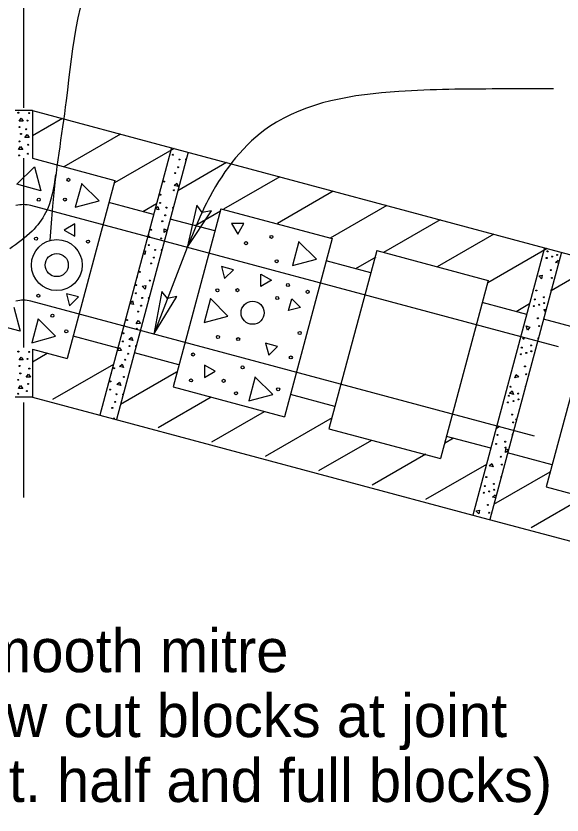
# Model space of a CAD drawing. Extents: x 0 to 2.83, y -0.03 to 1.83.
# Drawn here: x 0.4777 to 0.6421, y 0.6876 to 0.928 of the extents above; entities that cross this region are included whole.
import ezdxf

# ---------------------------------------------------------------- set-up
doc = ezdxf.new("R2010")
doc.units = 0
for name, color, linetype in [('50', 7, 'Continuous'), ('51', 7, 'Continuous'), ('52', 7, 'Continuous'), ('54', 7, 'Continuous'), ('55', 7, 'Continuous'), ('57', 7, 'Continuous'), ('58', 7, 'Continuous')]:
    doc.layers.add(name, color=color, linetype=linetype)

msp = doc.modelspace()

# ---------------------------------------------------------------- linework, layer by layer
at = {"layer": '50'}
for p, q in [((0.4774566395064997, 0.899610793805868), (0.4826566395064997, 0.899610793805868)), ((0.4826566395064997, 0.8995654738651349), (0.524515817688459, 0.8883493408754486)), ((0.4826566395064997, 0.8995654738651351), (0.4826566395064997, 0.8851923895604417)), ((0.524515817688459, 0.8883493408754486), (0.5029561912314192, 0.8078877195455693)), ((0.524515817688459, 0.8883493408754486), (0.6368207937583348, 0.8582573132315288)), ((0.4826566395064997, 0.8851923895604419), (0.5075122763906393, 0.8785323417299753)), ((0.529538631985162, 0.8870034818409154), (0.5079790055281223, 0.8065418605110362)), ((0.5075122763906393, 0.8785323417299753), (0.49313919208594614, 0.8248912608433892)), ((0.5191171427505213, 0.8682334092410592), (0.505706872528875, 0.8718266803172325)), ((0.5393556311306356, 0.8699999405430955), (0.5249825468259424, 0.8163588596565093)), ((0.5393556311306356, 0.8699999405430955), (0.5728893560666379, 0.8610146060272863)), ((0.5375502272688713, 0.8632942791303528), (0.5241399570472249, 0.8668875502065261)), ((0.5728893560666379, 0.8610146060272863), (0.5585162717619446, 0.8073735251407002)), ((0.5862996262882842, 0.857421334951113), (0.571926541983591, 0.8037802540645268)), ((0.5862996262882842, 0.857421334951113), (0.6198172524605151, 0.8484403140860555)), ((0.6368207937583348, 0.8582573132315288), (0.615261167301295, 0.7777956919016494)), ((0.6418597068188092, 0.8569071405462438), (0.6203000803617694, 0.7764455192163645)), ((0.6368207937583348, 0.8582573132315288), (0.7491418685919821, 0.8281609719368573)), ((0.5844942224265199, 0.8507156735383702), (0.5710839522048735, 0.8543089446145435)), ((0.6198172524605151, 0.8484403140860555), (0.6054441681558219, 0.7947992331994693)), ((0.6314382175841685, 0.8381370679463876), (0.6180279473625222, 0.8417303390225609)), ((0.6516767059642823, 0.839903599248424), (0.6373036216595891, 0.7862625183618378)), ((0.649871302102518, 0.8331979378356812), (0.6364610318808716, 0.8367912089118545)), ((0.5083387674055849, 0.82800796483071), (0.4949284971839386, 0.8316012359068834)), ((0.4826566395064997, 0.8277000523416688), (0.49313919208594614, 0.8248912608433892)), ((0.4826566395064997, 0.8277000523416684), (0.4826566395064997, 0.8133269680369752)), ((0.5267718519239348, 0.8230688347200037), (0.5133615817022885, 0.8266621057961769)), ((0.5249825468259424, 0.8163588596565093), (0.5585162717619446, 0.8073735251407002)), ((0.4774566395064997, 0.8133722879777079), (0.4826566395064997, 0.8133722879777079)), ((0.4826566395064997, 0.8133269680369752), (0.5029561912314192, 0.8078877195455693)), ((0.5737158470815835, 0.810490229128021), (0.5603055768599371, 0.8140835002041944)), ((0.5029561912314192, 0.8078877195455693), (0.615261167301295, 0.7777956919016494)), ((0.571926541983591, 0.8037802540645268), (0.6054441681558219, 0.7947992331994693)), ((0.6206598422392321, 0.7979116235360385), (0.6072495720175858, 0.8015048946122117)), ((0.639092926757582, 0.792972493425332), (0.6256826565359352, 0.7965657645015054)), ((0.6373036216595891, 0.7862625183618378), (0.67082124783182, 0.7772814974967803)), ((0.615261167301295, 0.7777956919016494), (0.7275822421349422, 0.7476993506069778))]:
    msp.add_line(p, q, dxfattribs=at)
for centre in [(0.493513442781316, 0.8786878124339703), (0.4845836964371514, 0.872706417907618), (0.49245140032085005, 0.8727393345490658), (0.48377012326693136, 0.8609843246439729), (0.5546186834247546, 0.8615091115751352), (0.49941355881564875, 0.8601223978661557), (0.5469472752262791, 0.8596262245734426), (0.5562011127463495, 0.8542044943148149), (0.5595652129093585, 0.8470255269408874), (0.4844703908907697, 0.8437985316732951), (0.538361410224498, 0.845452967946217), (0.5443681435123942, 0.84548092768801), (0.565494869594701, 0.8449791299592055), (0.556338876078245, 0.8431232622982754), (0.48869356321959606, 0.8378078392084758), (0.4928798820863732, 0.8330917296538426), (0.5385112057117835, 0.8314120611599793), (0.5631251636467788, 0.8326134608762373), (0.5445909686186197, 0.8307661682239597), (0.5310410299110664, 0.8261299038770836), (0.5604438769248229, 0.8252362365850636), (0.5459242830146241, 0.8222479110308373), (0.5304033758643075, 0.8183128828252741), (0.5402147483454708, 0.8182017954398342), (0.556635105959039, 0.8156581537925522), (0.5439470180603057, 0.8144768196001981)]:
    msp.add_circle(centre, 0.00045797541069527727, dxfattribs=at)
at = {"layer": '51'}
for p, q in [((0.483298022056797, 0.8825930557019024), (0.47802111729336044, 0.8773658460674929)), ((0.4832915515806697, 0.8826172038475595), (0.48521975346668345, 0.8754210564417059)), ((0.4974988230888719, 0.8776092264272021), (0.4955706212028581, 0.8704130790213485)), ((0.4974923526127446, 0.877585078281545), (0.5027692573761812, 0.8723578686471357)), ((0.48521975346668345, 0.8754210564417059), (0.47802974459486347, 0.8773336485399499)), ((0.6409597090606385, 0.8283963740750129), (0.48221876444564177, 0.8709308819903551)), ((0.4955706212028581, 0.8704130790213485), (0.5027606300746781, 0.8723256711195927)), ((0.5628759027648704, 0.8600914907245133), (0.5609477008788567, 0.8528953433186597)), ((0.5628694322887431, 0.860067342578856), (0.5681463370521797, 0.8548401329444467)), ((0.5609477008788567, 0.8528953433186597), (0.5681377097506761, 0.8548079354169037)), ((0.63377604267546, 0.801586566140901), (0.48221876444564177, 0.8421962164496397)), ((0.5362443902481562, 0.8429714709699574), (0.5343322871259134, 0.8357710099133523)), ((0.5362540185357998, 0.8429430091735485), (0.5415126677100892, 0.8377120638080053)), ((0.47704956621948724, 0.8403601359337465), (0.47896166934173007, 0.833159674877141)), ((0.4843597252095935, 0.8368804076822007), (0.4824476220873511, 0.8296799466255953)), ((0.48437151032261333, 0.8368599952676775), (0.4896301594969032, 0.831629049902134)), ((0.5343322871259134, 0.8357710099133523), (0.5415083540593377, 0.8376959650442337)), ((0.47896166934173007, 0.833159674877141), (0.47178560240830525, 0.8350846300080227)), ((0.4824476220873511, 0.8296799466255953), (0.48962368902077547, 0.8316049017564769)), ((0.549736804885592, 0.8193626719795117), (0.5478247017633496, 0.8121622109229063)), ((0.5497485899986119, 0.8193422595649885), (0.5550072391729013, 0.814111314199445)), ((0.5478247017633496, 0.8121622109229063), (0.555000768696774, 0.814087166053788))]:
    msp.add_line(p, q, dxfattribs=at)
for centre in [(0.49000834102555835, 0.8530289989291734), (0.5489396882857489, 0.838677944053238)]:
    msp.add_circle(centre, 0.0034722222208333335, dxfattribs=at)
for centre in [(0.4799720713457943, 0.8625461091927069), (0.4799720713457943, 0.8338114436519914)]:
    msp.add_arc(centre, 0.008680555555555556, 74.99999999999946, 104.99999999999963, dxfattribs=at)
at = {"layer": '52'}
for p, q in [((0.5463158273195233, 0.8655812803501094), (0.5425818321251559, 0.8655551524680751)), ((0.5425839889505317, 0.8655632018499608), (0.5444460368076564, 0.8623380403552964)), ((0.5444460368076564, 0.8623380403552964), (0.5463115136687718, 0.8655651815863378)), ((0.49540548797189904, 0.8654197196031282), (0.4921879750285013, 0.8635827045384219)), ((0.49219013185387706, 0.863574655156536), (0.4954131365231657, 0.8617206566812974)), ((0.4954131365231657, 0.8617206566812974), (0.49541942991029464, 0.8654320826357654)), ((0.539550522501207, 0.8525968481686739), (0.5405167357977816, 0.8489905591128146)), ((0.5431427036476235, 0.8516429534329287), (0.5395623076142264, 0.8525764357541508)), ((0.5405167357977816, 0.8489905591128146), (0.5431566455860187, 0.8516305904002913)), ((0.5513921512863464, 0.8466266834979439), (0.5513858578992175, 0.850338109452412)), ((0.5513997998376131, 0.8503257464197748), (0.5546173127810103, 0.8484887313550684)), ((0.554615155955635, 0.8484806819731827), (0.5513921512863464, 0.8466266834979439)), ((0.49651970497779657, 0.8434461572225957), (0.49292536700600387, 0.8443920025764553)), ((0.4929275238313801, 0.844400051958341), (0.493879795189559, 0.840806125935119)), ((0.493879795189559, 0.840806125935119), (0.49651754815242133, 0.84343810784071)), ((0.5597773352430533, 0.8393189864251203), (0.5607414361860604, 0.842917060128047)), ((0.5607392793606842, 0.8429090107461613), (0.5633696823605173, 0.8402975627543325)), ((0.563367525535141, 0.8402895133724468), (0.5597773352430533, 0.8393189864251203)), ((0.5564249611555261, 0.8285697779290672), (0.5528306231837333, 0.8295156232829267)), ((0.5528306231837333, 0.8295156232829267), (0.5537828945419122, 0.8259216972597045)), ((0.5537872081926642, 0.8259377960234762), (0.5564249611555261, 0.8285697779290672)), ((0.5344123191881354, 0.8229598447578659), (0.5344142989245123, 0.8192323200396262)), ((0.5376437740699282, 0.8211104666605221), (0.534426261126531, 0.8229474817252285)), ((0.5344142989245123, 0.8192323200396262), (0.5376416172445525, 0.8211024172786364))]:
    msp.add_line(p, q, dxfattribs=at)
at = {"layer": '54'}
for points in [[(0.529284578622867, 0.8583196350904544), (0.53656055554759, 0.8693416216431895), (0.5337844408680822, 0.8688845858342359), (0.5321086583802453, 0.8710747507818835)], [(0.5192398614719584, 0.8322764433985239), (0.5261308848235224, 0.8435431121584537), (0.5233722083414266, 0.8429904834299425), (0.5216217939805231, 0.8451214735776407)]]:
    msp.add_lwpolyline(points, close=True, dxfattribs=at)
at = {"layer": '55'}
for p, q in [((0.4799720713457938, 0.9799769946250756), (0.4799720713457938, 0.9003949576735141)), ((0.4799720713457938, 0.8852377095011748), (0.4799720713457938, 0.8282019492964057)), ((0.529284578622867, 0.8583196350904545), (0.5192398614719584, 0.8322764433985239)), ((0.4799720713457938, 0.811689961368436), (0.4799720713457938, 0.7831406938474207))]:
    msp.add_line(p, q, dxfattribs=at)
for points in [[(0.4786593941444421, 0.8963397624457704), (0.47928439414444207, 0.8972381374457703), (0.47990951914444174, 0.8963397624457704), (0.4786593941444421, 0.8963397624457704)], [(0.480439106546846, 0.8914013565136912), (0.481064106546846, 0.8922997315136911), (0.4816892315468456, 0.8914013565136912), (0.480439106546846, 0.8914013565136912)], [(0.47849809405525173, 0.8877908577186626), (0.4791230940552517, 0.8886892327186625), (0.47974821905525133, 0.8877908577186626), (0.47849809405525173, 0.8877908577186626)], [(0.5253327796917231, 0.8769874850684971), (0.5261689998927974, 0.8776934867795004), (0.5265403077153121, 0.8766639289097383), (0.5253327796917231, 0.8769874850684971)], [(0.5196089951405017, 0.8700368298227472), (0.520370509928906, 0.8706797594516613), (0.5207418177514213, 0.8696502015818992), (0.5195882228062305, 0.8699593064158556)], [(0.5223337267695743, 0.8628053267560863), (0.5223304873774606, 0.8638997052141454), (0.5232568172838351, 0.8635594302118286)], [(0.5232212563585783, 0.8634267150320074), (0.5223337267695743, 0.8628053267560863)], [(0.5161665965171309, 0.8571896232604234), (0.5166575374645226, 0.8572777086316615), (0.5164642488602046, 0.8562004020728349), (0.5160204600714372, 0.8566442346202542)], [(0.6400817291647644, 0.8538420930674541), (0.6409179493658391, 0.8545480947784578), (0.6410956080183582, 0.8540554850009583)], [(0.6409743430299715, 0.8536029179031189), (0.6400817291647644, 0.8538420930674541)], [(0.6350464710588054, 0.849756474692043), (0.6361237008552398, 0.8499497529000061), (0.6359304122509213, 0.8488724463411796), (0.6350464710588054, 0.849756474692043)], [(0.5156911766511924, 0.8466725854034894), (0.5167684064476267, 0.8468658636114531), (0.5165751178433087, 0.8457885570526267), (0.5156911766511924, 0.8466725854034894)], [(0.5119860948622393, 0.8415877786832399), (0.5127476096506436, 0.8422307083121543), (0.5131189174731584, 0.8412011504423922), (0.5119653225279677, 0.8415102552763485)], [(0.6366266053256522, 0.8396467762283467), (0.6372353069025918, 0.8396486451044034)], [(0.6370664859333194, 0.8390185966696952), (0.6366266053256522, 0.8396467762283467)], [(0.5139394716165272, 0.835384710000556), (0.5144838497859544, 0.8363340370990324), (0.5151848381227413, 0.8354935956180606), (0.5139394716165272, 0.835384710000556)], [(0.6313126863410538, 0.834708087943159), (0.6323421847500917, 0.8343368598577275), (0.6316363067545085, 0.8335005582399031), (0.6313126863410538, 0.834708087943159)], [(0.5117036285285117, 0.8306776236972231), (0.512539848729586, 0.8313836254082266), (0.5129111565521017, 0.8303540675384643), (0.5117036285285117, 0.8306776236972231)], [(0.5082741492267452, 0.8272712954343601), (0.5088184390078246, 0.8282207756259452), (0.5095195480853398, 0.8273803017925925), (0.5082741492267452, 0.8272712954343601)], [(0.4786593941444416, 0.8244743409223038), (0.47928439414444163, 0.8253727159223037), (0.47990951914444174, 0.8244743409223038), (0.4786593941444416, 0.8244743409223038)], [(0.5088360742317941, 0.8225243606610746), (0.5096722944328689, 0.8232303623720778), (0.5100436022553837, 0.8222008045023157), (0.5088360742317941, 0.8225243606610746)], [(0.4808395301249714, 0.819350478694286), (0.4814645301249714, 0.820248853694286), (0.48208965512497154, 0.819350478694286), (0.4808395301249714, 0.819350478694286)], [(0.6278833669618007, 0.8191051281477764), (0.6282544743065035, 0.820134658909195), (0.6290908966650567, 0.8194287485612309), (0.6278833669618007, 0.8191051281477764)], [(0.5080604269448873, 0.8170810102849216), (0.5088966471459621, 0.817787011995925), (0.5092679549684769, 0.8167574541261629), (0.5080604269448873, 0.8170810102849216)], [(0.47849809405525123, 0.8159254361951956), (0.4791230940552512, 0.8168238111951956), (0.47974821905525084, 0.8159254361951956), (0.47849809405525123, 0.8159254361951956)], [(0.6262363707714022, 0.8144508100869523), (0.6270725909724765, 0.8151568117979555), (0.6274438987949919, 0.8141272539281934), (0.6262363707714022, 0.8144508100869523)], [(0.5069652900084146, 0.8068134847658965), (0.5072385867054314, 0.8070442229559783), (0.5073599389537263, 0.8067077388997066)], [(0.6281080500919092, 0.8067153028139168), (0.62841109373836, 0.8067162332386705)], [(0.6283270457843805, 0.8064025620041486), (0.6281080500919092, 0.8067153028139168)], [(0.6222540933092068, 0.8037402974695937), (0.6222536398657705, 0.8038919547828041)], [(0.6224833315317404, 0.8047491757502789), (0.6232781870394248, 0.8044572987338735), (0.6222540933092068, 0.8037402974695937)], [(0.6250317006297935, 0.7966855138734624), (0.6251236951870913, 0.7977759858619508), (0.6259158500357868, 0.7974038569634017)], [(0.6258499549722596, 0.7971579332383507), (0.6250317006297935, 0.7966855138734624)], [(0.6201153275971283, 0.7926518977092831), (0.6209515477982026, 0.7933578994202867), (0.6213228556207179, 0.7923283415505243), (0.6201153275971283, 0.7926518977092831)], [(0.6211513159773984, 0.7831928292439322), (0.6219875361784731, 0.783898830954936), (0.6221651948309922, 0.7834062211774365)], [(0.6220439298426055, 0.7829536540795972), (0.6211513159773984, 0.7831928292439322)], [(0.6161160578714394, 0.7791072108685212), (0.6171932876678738, 0.7793004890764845), (0.6169999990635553, 0.7782231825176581), (0.6161160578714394, 0.7791072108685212)]]:
    msp.add_lwpolyline(points, dxfattribs=at)
for centre, radius in [((0.47843780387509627, 0.8988860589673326), 0.00015017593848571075), ((0.4817117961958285, 0.8987860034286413), 0.00015017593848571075), ((0.47880839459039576, 0.894538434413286), 0.00015017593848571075), ((0.4811621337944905, 0.8964937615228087), 0.00015017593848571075), ((0.47923930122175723, 0.8925103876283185), 0.00015017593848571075), ((0.4808136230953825, 0.8939098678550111), 0.00015017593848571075), ((0.4787494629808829, 0.8902257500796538), 0.00015017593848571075), ((0.4813941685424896, 0.8892415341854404), 0.00015017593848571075), ((0.47864891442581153, 0.8860225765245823), 0.00015017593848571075), ((0.481318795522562, 0.8865279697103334), 0.00015017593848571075), ((0.5249649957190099, 0.8862347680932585), 0.00015017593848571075), ((0.5268984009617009, 0.8848019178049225), 0.00015017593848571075), ((0.5265237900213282, 0.882493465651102), 0.00015017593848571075), ((0.5256508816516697, 0.8807150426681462), 0.00015017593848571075), ((0.5223144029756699, 0.8781633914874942), 0.00015017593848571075), ((0.5252709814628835, 0.875541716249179), 0.00015017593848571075), ((0.5212165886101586, 0.8741797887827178), 0.00015017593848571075), ((0.5210827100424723, 0.8717458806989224), 0.00015017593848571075), ((0.5230161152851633, 0.8703130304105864), 0.00015017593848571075), ((0.5226415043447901, 0.8680045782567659), 0.00015017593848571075), ((0.5217685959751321, 0.8662261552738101), 0.00015017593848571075), ((0.5184321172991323, 0.8636745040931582), 0.00015017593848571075), ((0.5178153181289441, 0.8614860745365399), 0.00015017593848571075), ((0.5213886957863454, 0.8610528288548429), 0.00015017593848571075), ((0.4900083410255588, 0.8530289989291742), 0.007657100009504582), ((0.5176814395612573, 0.8590521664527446), 0.00015017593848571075), ((0.5196148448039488, 0.8576193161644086), 0.00015017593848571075), ((0.6377260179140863, 0.8571679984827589), 0.00015017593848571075), ((0.6405883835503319, 0.8560961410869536), 0.00015017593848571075), ((0.5183673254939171, 0.8535324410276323), 0.00015017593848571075), ((0.519240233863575, 0.8553108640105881), 0.00015017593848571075), ((0.6374330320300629, 0.8551641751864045), 0.00015017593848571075), ((0.6390772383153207, 0.85557732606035), 0.00015017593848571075), ((0.5150308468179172, 0.8509807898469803), 0.00015017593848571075), ((0.6386871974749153, 0.8515044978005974), 0.00015017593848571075), ((0.6390334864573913, 0.8491553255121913), 0.00015017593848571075), ((0.5139330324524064, 0.846997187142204), 0.00015017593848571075), ((0.5179874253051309, 0.8483591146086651), 0.00015017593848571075), ((0.5137991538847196, 0.8445632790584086), 0.00015017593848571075), ((0.6343250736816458, 0.8453858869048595), 0.00015017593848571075), ((0.5157325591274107, 0.8431304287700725), 0.00015017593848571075), ((0.6338437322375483, 0.8426791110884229), 0.00015017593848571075), ((0.6366285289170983, 0.8433660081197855), 0.00015017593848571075), ((0.6367060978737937, 0.8416072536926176), 0.00015017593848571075), ((0.514485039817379, 0.8390435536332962), 0.00015017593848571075), ((0.5153579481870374, 0.840821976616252), 0.00015017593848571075), ((0.6335507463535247, 0.8406752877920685), 0.00015017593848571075), ((0.6351949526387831, 0.8410884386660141), 0.00015017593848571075), ((0.6348049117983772, 0.8370156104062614), 0.00015017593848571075), ((0.5111485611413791, 0.8364919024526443), 0.00015017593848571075), ((0.6351512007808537, 0.8346664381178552), 0.00015017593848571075), ((0.5100507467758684, 0.8325082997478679), 0.00015017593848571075), ((0.5141051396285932, 0.833870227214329), 0.00015017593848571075), ((0.509916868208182, 0.8300743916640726), 0.00015017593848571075), ((0.6304427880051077, 0.8308969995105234), 0.00015017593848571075), ((0.47843780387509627, 0.8270206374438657), 0.00015017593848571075), ((0.481711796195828, 0.8269205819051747), 0.00015017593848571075), ((0.5118502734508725, 0.8286415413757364), 0.00015017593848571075), ((0.6299614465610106, 0.8281902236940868), 0.00015017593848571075), ((0.6327462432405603, 0.8288771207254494), 0.00015017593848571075), ((0.6328238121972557, 0.8271183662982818), 0.00015017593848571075), ((0.48122375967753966, 0.8247828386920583), 0.00015017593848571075), ((0.5106027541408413, 0.8245546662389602), 0.00015017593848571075), ((0.5114756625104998, 0.8263330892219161), 0.00015017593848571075), ((0.6296684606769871, 0.8261864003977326), 0.00015017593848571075), ((0.6313126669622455, 0.8265995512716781), 0.00015017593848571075), ((0.47880839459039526, 0.8226730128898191), 0.00015017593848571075), ((0.6309226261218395, 0.8225267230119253), 0.00015017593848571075), ((0.4790306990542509, 0.8204427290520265), 0.00015017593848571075), ((0.4817417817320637, 0.8218820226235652), 0.00015017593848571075), ((0.5072662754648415, 0.8220030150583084), 0.00015017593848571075), ((0.6312689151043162, 0.8201775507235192), 0.00015017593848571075), ((0.4784080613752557, 0.8185067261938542), 0.00015017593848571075), ((0.5061684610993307, 0.8180194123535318), 0.00015017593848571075), ((0.5102228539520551, 0.819381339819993), 0.00015017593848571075), ((0.4810236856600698, 0.815116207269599), 0.00015017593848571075), ((0.4813747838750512, 0.8172757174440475), 0.00015017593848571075), ((0.5060345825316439, 0.8155855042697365), 0.00015017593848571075), ((0.6265605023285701, 0.8164081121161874), 0.00015017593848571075), ((0.4784102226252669, 0.8143116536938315), 0.00015017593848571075), ((0.5079679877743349, 0.8141526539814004), 0.00015017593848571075), ((0.626079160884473, 0.8137013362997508), 0.00015017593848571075), ((0.6288639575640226, 0.8143882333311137), 0.00015017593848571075), ((0.628941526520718, 0.8126294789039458), 0.00015017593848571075), ((0.5075933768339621, 0.81184420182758), 0.00015017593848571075), ((0.6257861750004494, 0.8116975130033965), 0.00015017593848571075), ((0.6274303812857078, 0.812110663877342), 0.00015017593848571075), ((0.5067204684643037, 0.8100657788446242), 0.00015017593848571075), ((0.6270403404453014, 0.8080378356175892), 0.00015017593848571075), ((0.627386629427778, 0.8056886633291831), 0.00015017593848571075), ((0.6226782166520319, 0.8019192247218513), 0.00015017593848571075), ((0.6221968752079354, 0.7992124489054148), 0.00015017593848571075), ((0.624981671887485, 0.7998993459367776), 0.00015017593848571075), ((0.6250592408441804, 0.7981405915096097), 0.00015017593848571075), ((0.6236390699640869, 0.7953441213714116), 0.00015017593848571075), ((0.6239853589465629, 0.7929949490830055), 0.00015017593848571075), ((0.6192769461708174, 0.7892255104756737), 0.00015017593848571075), ((0.6187956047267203, 0.7865187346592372), 0.00015017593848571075), ((0.6215804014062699, 0.7872056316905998), 0.00015017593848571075), ((0.6185026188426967, 0.784514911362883), 0.00015017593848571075), ((0.6201468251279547, 0.7849280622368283), 0.00015017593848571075), ((0.6216579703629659, 0.7854468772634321), 0.00015017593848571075), ((0.6197567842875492, 0.7808552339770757), 0.00015017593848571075), ((0.6201030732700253, 0.7785060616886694), 0.00015017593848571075)]:
    msp.add_circle(centre, radius, dxfattribs=at)
for centre, start, end in [((0.528862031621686, 0.8847332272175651), 48.94572428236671, 281.05427571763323), ((0.521401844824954, 0.8765784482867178), 240.08057103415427, 89.91942896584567), ((0.5249797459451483, 0.8702443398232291), 48.945724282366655, 281.05427571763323), ((0.5175195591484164, 0.8620895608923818), 240.08057103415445, 89.91942896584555), ((0.5215784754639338, 0.8575506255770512), 48.94572428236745, 281.05427571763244), ((0.5141182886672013, 0.8493958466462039), 240.0805710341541, 89.9194289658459), ((0.638835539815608, 0.8454579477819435), 91.29949940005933, 238.70050059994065), ((0.5176961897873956, 0.8430617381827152), 48.94572428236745, 281.05427571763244), ((0.5102360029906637, 0.8349069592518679), 240.08057103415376, 89.91942896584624), ((0.6349532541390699, 0.8309690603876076), 91.29949940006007, 238.70050059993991), ((0.5138139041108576, 0.8285728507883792), 48.94572428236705, 281.0542757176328), ((0.5063537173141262, 0.8204180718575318), 240.08057103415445, 89.91942896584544), ((0.6310709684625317, 0.8164801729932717), 91.29949940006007, 238.70050059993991), ((0.5099316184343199, 0.8140839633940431), 48.945724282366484, 281.05427571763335), ((0.6271886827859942, 0.8019912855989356), 91.29949940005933, 238.70050059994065), ((0.6237874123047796, 0.789297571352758), 91.29949940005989, 238.70050059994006)]:
    msp.add_arc(centre, 0.00015017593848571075, start, end, dxfattribs=at)
for points in [[(0.5260705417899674, 0.963329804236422), (0.5210756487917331, 0.963329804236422), (0.5056057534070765, 0.9510080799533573), (0.49282029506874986, 0.9025470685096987), (0.48869595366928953, 0.8707896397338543), (0.4879615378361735, 0.8604074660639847)], [(0.6395170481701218, 0.906018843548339), (0.6228943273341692, 0.906018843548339), (0.5929091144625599, 0.9052641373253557), (0.5540231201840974, 0.8947015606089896), (0.5360338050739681, 0.8735764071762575), (0.529284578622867, 0.8583196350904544)], [(0.4896486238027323, 0.8802851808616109), (0.4866435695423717, 0.8687519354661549), (0.482575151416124, 0.8632595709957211), (0.4758372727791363, 0.8579079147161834)]]:
    msp.add_spline(points, degree=3, dxfattribs=at)
at = {"layer": '58'}
for p, q in [((0.5732306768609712, 0.875296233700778), (0.5563904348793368, 0.865573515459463)), ((0.5893294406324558, 0.8709825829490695), (0.5723258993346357, 0.8611655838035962))]:
    msp.add_line(p, q, dxfattribs=at)
for points in [[(0.49175483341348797, 0.8971276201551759), (0.4826566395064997, 0.8918784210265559)], [(0.5092219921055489, 0.8924473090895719), (0.4921368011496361, 0.8825831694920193)], [(0.5253207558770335, 0.8881336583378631), (0.5073782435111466, 0.8777745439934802)], [(0.5411050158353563, 0.8838697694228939), (0.5264306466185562, 0.8754043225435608)], [(0.5571319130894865, 0.8796098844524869), (0.540150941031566, 0.8698127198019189)], [(0.5199886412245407, 0.8714536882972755), (0.515904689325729, 0.8690941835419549)], [(0.5392710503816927, 0.869297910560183), (0.5316196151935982, 0.8648833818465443)], [(0.6054282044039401, 0.8666689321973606), (0.5883226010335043, 0.8567930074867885)], [(0.6215269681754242, 0.8623552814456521), (0.6044417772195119, 0.8524911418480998)], [(0.6376257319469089, 0.8580416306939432), (0.6196832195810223, 0.8476825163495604)], [(0.5859977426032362, 0.8554575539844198), (0.5799142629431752, 0.8519428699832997)], [(0.6534099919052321, 0.853777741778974), (0.6387517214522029, 0.8453079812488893)], [(0.6322936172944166, 0.8413616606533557), (0.6282096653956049, 0.8390021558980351)], [(0.4870676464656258, 0.8263800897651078), (0.4826566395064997, 0.8238333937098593)], [(0.507047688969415, 0.8231573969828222), (0.4886947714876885, 0.8125545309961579)], [(0.5260464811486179, 0.8208446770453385), (0.5091450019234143, 0.8110866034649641)], [(0.5364684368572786, 0.8132467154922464), (0.5205059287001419, 0.8040307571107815)], [(0.5524447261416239, 0.808862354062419), (0.5366046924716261, 0.799717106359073)], [(0.5728505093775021, 0.807035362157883), (0.5527034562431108, 0.7954034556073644)], [(0.609408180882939, 0.8009264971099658), (0.6066402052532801, 0.7993272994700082)], [(0.5847239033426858, 0.8002821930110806), (0.5688022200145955, 0.7910898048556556)], [(0.601110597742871, 0.7961415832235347), (0.5849009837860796, 0.786776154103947)], [(0.6193526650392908, 0.7930653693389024), (0.6009997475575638, 0.7824625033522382)], [(0.6383675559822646, 0.7907483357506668), (0.621466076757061, 0.7809902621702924)], [(0.648773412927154, 0.7831546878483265), (0.6328109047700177, 0.7739387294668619)]]:
    msp.add_lwpolyline(points, dxfattribs=at)

# ---------------------------------------------------------------- texts
at = {"layer": '57'}
for s, p in [('Smooth mitre', (0.45622653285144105, 0.7305316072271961)), ('saw cut blocks at joint', (0.45622653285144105, 0.7110066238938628)), ('(alt. half and full blocks)', (0.45622653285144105, 0.6914816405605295))]:
    msp.add_text(s, height=0.013016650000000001, dxfattribs=at).set_placement(p)

doc.saveas('drawing.dxf')
